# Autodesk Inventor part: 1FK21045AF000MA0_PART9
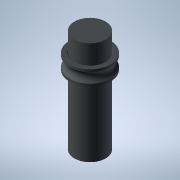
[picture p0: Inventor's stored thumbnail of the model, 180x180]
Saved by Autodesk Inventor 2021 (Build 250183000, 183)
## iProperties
Created: 2025-04
Part Number: 1FK21045AF000MA0_PART9
Material: Generic
Catalog Web Link: www.3dfindit.com
Description: -Servo synchronous motor
Document SubType Name: Modeling
Designer: psAdmin
Mass: 18.6788 g
Surface Area: 52.316 cm^2
Volume: 18.6788 cm^3
Density: 1 g/cm^3
Appearance: PSOLRGB-212-217-219
Category: PARTsolutions
Title: 1FK21045AF000MA0_PART9
Author: Cadenas PARTsolutions
Comments: Servo synchronous motor
Sending System: PARTsolutions
Preprocessor: ST-DEVELOPER v19.3
PSOL_IDENT_0: {$CADENAS_DATA/23d-libs/siemens_ag/_cat_/8b/0a/1fk21045af000ma0.prj},213 {VTYP=3D},{NB=1FK21045AF000
PSOL_IDENT_1: MA0_PART9},{LINA=1FK21045AF000MA0_PART9},{NN=1FK21045AF000MA0_PART9},{NOPRJ=TRUE},{DATE=19.08.2025 1
PSOL_IDENT_2: 4:00:48},{GEOMDATE=30.07.2025 02:00:28},{VERSION=},{LINEID=10},{WBVAR=},{WBNUMERIC=}  {NB=1FK21045AF
PSOL_IDENT_3: 000MA0_PART9},{LINA=1FK21045AF000MA0_PART9},{KT=DUMMY},{PREVIEW=../../../_pool_/a9/69/p_d211_xx_0081
PSOL_IDENT_4: 8j.png},{DESCSHORT=SIMOTICS S-1FK2 HD, SINAMICS S210 3AC 400V-480V, 2.4 Nm, 3000 rpm},{DESCLONG=SIMO
PSOL_IDENT_5: TICS S-1FK2 HD servo motor M0=2.4 Nm; PN = 0.75 kW at nN=3000 rpm (380-480 V); PN = 0.375 kW at nN=1
PSOL_IDENT_6: 500 rpm (200-240 V); degree of protection IP64; cylindrical shaft D19x40mm; absolute encoder 22-bit
PSOL_IDENT_7: + 12-bit multiturn (encoder AM22DQC); with OCC interface; plug size M17, rotatable; SIMOTICS S-1FK2
PSOL_IDENT_8: servomotorfor a wide range of uses in industrial environments. SIMOTICS S‑1FK2 servomotors are compa
PSOL_IDENT_9: ct synchronous motors with a high dynamic performance that set themselves apart as a result of their
PSOL_IDENT_10: high power density, degree of protection and overload capability. The motors are available in two v
PSOL_IDENT_11: ariants: as High Dynamic variant (highest dynamic performance as a result of the low intrinsic momen
PSOL_IDENT_12: t of inertia for applications demanding a high dynamic performance with low moved masses) - and as C
PSOL_IDENT_13: ompact variant (precise and stable closed-loop control for medium up to large moved masses as a resu
PSOL_IDENT_14: lt of a medium intrinsic moment of inertia). SIMOTICSS‑1FK2 servomotors fully exploit their strength
PSOL_IDENT_15: s in a system with the SINAMICSS210 frequency converter and simple connection using the one cable co
PSOL_IDENT_16: nnection (OCC). Advantages include the short control and positioning times, fast and precise correct
PSOL_IDENT_17: ion of disturbing quantities as well as stable control with a high dynamic performance. The servo mo
PSOL_IDENT_18: tors can be configured to address a wide range of requirements. For example with and without holding
PSOL_IDENT_19: brake, IP64 or IP65 degree of protection, singleturn or multiturn absolute encoders - to name just
PSOL_IDENT_20: a few. Further, the servomotors are available in different shaft heights extending from 20 to 100. A
PSOL_IDENT_21: shaft sealing ring is available to achieve an IP65 degree of protection and for subsequent mounting
PSOL_IDENT_22: at the motor or as spare part. SIMOTICS - the optimum motor for each and every motion control appli
PSOL_IDENT_23: cation.},{INTNO=195125050112},{SUPPLIERALTNO=1FK2104-5AF00-0MA0},{MANUID=1FK21045AF000MA0},{MANUNAME=
PSOL_IDENT_24: Siemens},{MANUTYPEDESC=Synchronous motor 1FK2-HD 2.4 NM},{AAU732=SIMOTICS},{AAO057=S-1FK2},{AAU734=S
PSOL_IDENT_25: IMOTICS S-1FK2 HD servo motor M0=2.4 Nm; PN = 0.75 kW at nN=3000 rpm (380-480 V); PN = 0.375 kW at n
PSOL_IDENT_26: N=1500 rpm (200-240 V); degree of protection IP64; cylindrical shaft D19x40mm; absolute encoder 22-b
PSOL_IDENT_27: it + 12-bit multiturn (encoder AM22DQC); with OCC interface; plug size M17, rotatable;},{AAW338=Sync
PSOL_IDENT_28: hronous motor 1FK2-HD 2.4 NM},{AAO742=SIMOTICS},{AAO663=4042948692912},{NOCUPEROU=1},{PRICEQUANTITY=
PSOL_IDENT_29: 1},{QUANTITYMIN=1},{QUANTITYINT=1},{CTN=85015100},{COO=DE},{AAO676=1FK2104-5AF00-0MA0},{AAO677=Sieme
PSOL_IDENT_30: ns AG},{ORDERUNIT=C62},{CONTENTUNIT=C62}
NB: 1FK21045AF000MA0_PART9
NT: Servo synchronous motor
NBSYN: $MANUID._PART9
LINA: 1FK21045AF000MA0_PART9
CATALOG: SIEMENS
PREVIEW: ../../../_pool_/a9/69/p_d211_xx_00818j.png
DESCSHORT: SIMOTICS S-1FK2 HD, SINAMICS S210 3AC 400V-480V, 2.4 Nm, 3000 rpm
DESCLONG: SIMOTICS S-1FK2 HD servo motor M0=2.4 Nm; PN = 0.75 kW at nN=3000 rpm (380-480 V); PN = 0.375 kW at nN=1500 rpm (200-240 V); degree of protection IP64; cylindri
INTNO: 195125050112
SUPPLIERALTNO: 1FK2104-5AF00-0MA0
MANUID: 1FK21045AF000MA0
MANUNAME: Siemens
MANUTYPEDESC: Synchronous motor 1FK2-HD 2.4 NM
AAU732: SIMOTICS
AAO057: S-1FK2
AAU734: SIMOTICS S-1FK2 HD servo motor M0=2.4 Nm; PN = 0.75 kW at nN=3000 rpm (380-480 V); PN = 0.375 kW at nN=1500 rpm (200-240 V); degree of protection IP64; cylindri
AAW338: Synchronous motor 1FK2-HD 2.4 NM
AAO742: SIMOTICS
AAO663: 4042948692912.0
NOCUPEROU: 1
PRICEQUANTITY: 1
QUANTITYMIN: 1
QUANTITYINT: 1
CTN: 85015100
COO: DE
ARTICLENO: 1FK21045AF000MA0_PART9
BOMINFO: 1FK21045AF000MA0_PART9
CREATOR: CADENAS GmbH
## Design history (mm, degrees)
feature "2025_04_17_15_40_42_0766"
body "Solid1"
